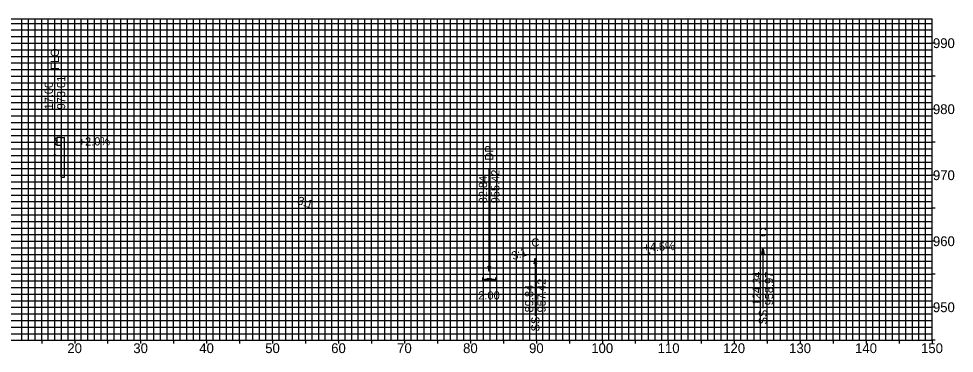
# Model space of a CAD drawing. Extents: x -153 to 153, y 943 to 994.
# Drawn here: x 11.5 to 153.4, y 943 to 993.7 of the extents above; entities that cross this region are included whole.
import ezdxf

# ---------------------------------------------------------------- set-up
doc = ezdxf.new("R2010")
doc.units = 0
for name, color, linetype in [('Default', 7, 'Continuous'), ('E_NCDOT_Terrain_Model_Boundary', 7, 'Continuous'), ('E_NCDOT_Terrain_Model_Breakline', 7, 'Continuous'), ('E_NCDOT_Terrain_Model_Contour_Imported', 7, 'Continuous'), ('E_NCDOT_Terrain_Model_Island', 7, 'Continuous'), ('E_NCDOT_Terrain_Model_Points_High', 7, 'Continuous'), ('E_NCDOT_Terrain_Model_Points_Low', 7, 'Continuous'), ('P_NCDOT_XS_Label_Grading_Side_Slope', 7, 'Continuous'), ('P_NCDOT_XS_Label_Slope_Superelevation', 7, 'Continuous'), ('Prop XS Grade Point', 7, 'Continuous'), ('Prop XS Label Slope Superelevation', 7, 'Continuous'), ('Prop XSC Text', 7, 'Continuous'), ('Sheet_Data_Field_CELL', 7, 'Continuous'), ('Sheet_RDY_Sticker_Preliminary_CELL', 7, 'Continuous'), ('Sheet_Sticker_Incomplete_CELL', 7, 'Continuous')]:
    doc.layers.add(name, color=color, linetype=linetype)

msp = doc.modelspace()

# ---------------------------------------------------------------- linework, layer by layer
at = {"layer": 'Default'}
msp.add_line((107.09, 958.2), (107.09, 958.2), dxfattribs=at)
at = {"layer": 'E_NCDOT_Terrain_Model_Breakline'}
for p, q in [((-150, 993), (150, 993)), ((12, 945), (12, 993.7)), ((13, 945), (13, 993.7)), ((14, 945), (14, 993.7)), ((16, 945), (16, 993.7)), ((17, 945), (17, 993.7)), ((18, 945), (18, 993.7)), ((19, 945), (19, 993.7)), ((21, 945), (21, 993.7)), ((22, 945), (22, 993.7)), ((23, 945), (23, 993.7)), ((24, 945), (24, 993.7)), ((26, 945), (26, 993.7)), ((27, 945), (27, 993.7)), ((28, 945), (28, 993.7)), ((29, 945), (29, 993.7)), ((31, 945), (31, 993.7)), ((32, 945), (32, 993.7)), ((33, 945), (33, 993.7)), ((34, 945), (34, 993.7)), ((36, 945), (36, 993.7)), ((37, 945), (37, 993.7)), ((38, 945), (38, 993.7)), ((39, 945), (39, 993.7)), ((41, 945), (41, 993.7)), ((42, 945), (42, 993.7)), ((43, 945), (43, 993.7)), ((44, 945), (44, 993.7)), ((46, 945), (46, 993.7)), ((47, 945), (47, 993.7)), ((48, 945), (48, 993.7)), ((49, 945), (49, 993.7)), ((51, 945), (51, 993.7)), ((52, 945), (52, 993.7)), ((53, 945), (53, 993.7)), ((54, 945), (54, 993.7)), ((56, 945), (56, 993.7)), ((57, 945), (57, 993.7)), ((58, 945), (58, 993.7)), ((59, 945), (59, 993.7)), ((61, 945), (61, 993.7)), ((62, 945), (62, 993.7)), ((63, 945), (63, 993.7)), ((64, 945), (64, 993.7)), ((66, 945), (66, 993.7)), ((67, 945), (67, 993.7)), ((68, 945), (68, 993.7)), ((69, 945), (69, 993.7)), ((71, 945), (71, 993.7)), ((72, 945), (72, 993.7)), ((73, 945), (73, 993.7)), ((74, 945), (74, 993.7)), ((76, 945), (76, 993.7)), ((77, 945), (77, 993.7)), ((78, 945), (78, 993.7)), ((79, 945), (79, 993.7)), ((81, 945), (81, 993.7)), ((82, 945), (82, 993.7)), ((83, 945), (83, 993.7)), ((84, 945), (84, 993.7)), ((86, 945), (86, 993.7)), ((87, 945), (87, 993.7)), ((88, 945), (88, 993.7)), ((89, 945), (89, 993.7)), ((91, 945), (91, 993.7)), ((92, 945), (92, 993.7)), ((93, 945), (93, 993.7)), ((94, 945), (94, 993.7)), ((96, 945), (96, 993.7)), ((97, 945), (97, 993.7)), ((98, 945), (98, 993.7)), ((99, 945), (99, 993.7)), ((101, 945), (101, 993.7)), ((102, 945), (102, 993.7)), ((103, 945), (103, 993.7)), ((104, 945), (104, 993.7)), ((106, 945), (106, 993.7)), ((107, 945), (107, 993.7)), ((108, 945), (108, 993.7)), ((109, 945), (109, 993.7)), ((111, 945), (111, 993.7)), ((112, 945), (112, 993.7)), ((113, 945), (113, 993.7)), ((114, 945), (114, 993.7)), ((116, 945), (116, 993.7)), ((117, 945), (117, 993.7)), ((118, 945), (118, 993.7)), ((119, 945), (119, 993.7)), ((121, 945), (121, 993.7)), ((122, 945), (122, 993.7)), ((123, 945), (123, 993.7)), ((124, 945), (124, 993.7)), ((126, 945), (126, 993.7)), ((127, 945), (127, 993.7)), ((128, 945), (128, 993.7)), ((129, 945), (129, 993.7)), ((131, 945), (131, 993.7)), ((132, 945), (132, 993.7)), ((133, 945), (133, 993.7)), ((134, 945), (134, 993.7)), ((136, 945), (136, 993.7)), ((137, 945), (137, 993.7)), ((138, 945), (138, 993.7)), ((139, 945), (139, 993.7)), ((141, 945), (141, 993.7)), ((142, 945), (142, 993.7)), ((143, 945), (143, 993.7)), ((144, 945), (144, 993.7)), ((146, 945), (146, 993.7)), ((147, 945), (147, 993.7)), ((148, 945), (148, 993.7)), ((149, 945), (149, 993.7)), ((-150, 992), (150, 992)), ((-150, 991), (150, 991)), ((-150, 989), (150, 989)), ((-150, 988), (150, 988)), ((-150, 987), (150, 987)), ((-150, 986), (150, 986)), ((-150, 984), (150, 984)), ((-150, 983), (150, 983)), ((-150, 982), (150, 982)), ((-150, 981), (150, 981)), ((-150, 979), (150, 979)), ((-150, 978), (150, 978)), ((-150, 977), (150, 977)), ((-150, 976), (150, 976)), ((-150, 974), (150, 974)), ((-150, 973), (150, 973)), ((-150, 972), (150, 972)), ((-150, 971), (150, 971)), ((-150, 969), (150, 969)), ((-150, 968), (150, 968)), ((-150, 967), (150, 967)), ((-150, 966), (150, 966)), ((-150, 964), (150, 964)), ((-150, 963), (150, 963)), ((-150, 962), (150, 962)), ((-150, 961), (150, 961)), ((-150, 959), (150, 959)), ((-150, 958), (150, 958)), ((-150, 957), (150, 957)), ((-150, 956), (150, 956)), ((-150, 954), (150, 954)), ((-150, 953), (150, 953)), ((-150, 952), (150, 952)), ((-150, 951), (150, 951)), ((-150, 949), (150, 949)), ((-150, 948), (150, 948)), ((-150, 947), (150, 947)), ((-150, 946), (150, 946))]:
    msp.add_line(p, q, dxfattribs=at)
at = {"layer": 'E_NCDOT_Terrain_Model_Contour_Imported'}
msp.add_circle((107.09, 958.2), 0.05, dxfattribs=at)
at = {"layer": 'E_NCDOT_Terrain_Model_Island'}
for p, q in [((20, 945), (20, 993.7)), ((30, 945), (30, 993.7)), ((40, 945), (40, 993.7)), ((50, 945), (50, 993.7)), ((60, 945), (60, 993.7)), ((70, 945), (70, 993.7)), ((80, 945), (80, 993.7)), ((90, 945), (90, 993.7)), ((100, 945), (100, 993.7)), ((110, 945), (110, 993.7)), ((120, 945), (120, 993.7)), ((130, 945), (130, 993.7)), ((140, 945), (140, 993.7)), ((-150, 990), (150, 990)), ((-150, 980), (150, 980)), ((-150, 970), (150, 970)), ((-150, 960), (150, 960)), ((-150, 950), (150, 950))]:
    msp.add_line(p, q, dxfattribs=at)
at = {"layer": 'E_NCDOT_Terrain_Model_Points_High'}
for p, q in [((15, 945), (15, 993.7)), ((20, 945), (20, 993.7)), ((25, 945), (25, 993.7)), ((30, 945), (30, 993.7)), ((35, 945), (35, 993.7)), ((40, 945), (40, 993.7)), ((45, 945), (45, 993.7)), ((50, 945), (50, 993.7)), ((55, 945), (55, 993.7)), ((60, 945), (60, 993.7)), ((65, 945), (65, 993.7)), ((70, 945), (70, 993.7)), ((75, 945), (75, 993.7)), ((80, 945), (80, 993.7)), ((85, 945), (85, 993.7)), ((90, 945), (90, 993.7)), ((95, 945), (95, 993.7)), ((100, 945), (100, 993.7)), ((105, 945), (105, 993.7)), ((110, 945), (110, 993.7)), ((115, 945), (115, 993.7)), ((120, 945), (120, 993.7)), ((125, 945), (125, 993.7)), ((130, 945), (130, 993.7)), ((135, 945), (135, 993.7)), ((140, 945), (140, 993.7)), ((145, 945), (145, 993.7)), ((-150, 990), (150, 990)), ((150.48, 990), (150, 990)), ((-150, 985), (150, 985)), ((150.48, 985), (150, 985)), ((-150, 980), (150, 980)), ((150.48, 980), (150, 980)), ((-150, 975), (150, 975)), ((150.48, 975), (150, 975)), ((-150, 970), (150, 970)), ((150.48, 970), (150, 970)), ((-150, 965), (150, 965)), ((150.48, 965), (150, 965)), ((-150, 960), (150, 960)), ((150.48, 960), (150, 960)), ((-150, 955), (150, 955)), ((150.48, 955), (150, 955)), ((-150, 950), (150, 950)), ((150.48, 950), (150, 950)), ((15, 945), (15, 944.52)), ((20, 945), (20, 944.52)), ((25, 945), (25, 944.52)), ((30, 945), (30, 944.52)), ((35, 945), (35, 944.52)), ((40, 945), (40, 944.52)), ((45, 945), (45, 944.52)), ((50, 945), (50, 944.52)), ((55, 945), (55, 944.52)), ((60, 945), (60, 944.52)), ((65, 945), (65, 944.52)), ((70, 945), (70, 944.52)), ((75, 945), (75, 944.52)), ((80, 945), (80, 944.52)), ((85, 945), (85, 944.52)), ((90, 945), (90, 944.52)), ((95, 945), (95, 944.52)), ((100, 945), (100, 944.52)), ((105, 945), (105, 944.52)), ((110, 945), (110, 944.52)), ((115, 945), (115, 944.52)), ((120, 945), (120, 944.52)), ((125, 945), (125, 944.52)), ((130, 945), (130, 944.52)), ((135, 945), (135, 944.52)), ((140, 945), (140, 944.52)), ((145, 945), (145, 944.52)), ((150, 945), (150, 944.52)), ((150.48, 945), (150, 945))]:
    msp.add_line(p, q, dxfattribs=at)
at = {"layer": 'E_NCDOT_Terrain_Model_Points_Low'}
for p, q in [((-150, 993.7), (150, 993.7)), ((150, 945), (150, 993.7)), ((-150, 945), (150, 945))]:
    msp.add_line(p, q, dxfattribs=at)
at = {"layer": 'Prop XS Grade Point'}
for p, q in [((17, 973.01), (17, 985.49)), ((82.84, 955.42), (82.84, 971.02)), ((124.34, 958.97), (124.34, 949.87)), ((89.84, 957.42), (89.84, 948.75)), ((89.84, 957.42), (89.84, 948.68)), ((81.84, 954.52), (81.84, 953.92)), ((81.84, 954.22), (83.84, 954.22)), ((83.84, 953.92), (83.84, 954.52))]:
    msp.add_line(p, q, dxfattribs=at)
for points in [[(124.34, 958.97), (124.52, 958.15), (124.17, 958.15)], [(82.84, 955.42), (82.67, 956.25), (83.02, 956.25)], [(89.84, 957.42), (90.02, 956.6), (89.67, 956.6)], [(89.84, 957.42), (90.02, 956.6), (89.67, 956.6)], [(89.84, 957.42), (90.02, 956.6), (89.67, 956.6)], [(81.84, 954.22), (83.03, 954.42), (83.03, 954.03)], [(83.84, 954.22), (82.66, 954.03), (82.66, 954.42)]]:
    msp.add_lwpolyline(points, close=True, dxfattribs=at)
msp.add_circle((17, 973.01), 0.12, dxfattribs=at)
at = {"layer": 'Prop XSC Text'}
for p, q in [((17.17, 975.62), (17.03, 975.52)), ((17.03, 975.39), (17.24, 975.25)), ((17.24, 975.03), (17.03, 974.88)), ((17.03, 974.75), (17.17, 974.66)), ((17.27, 975.64), (17.18, 975.63)), ((17.18, 974.65), (17.27, 974.63)), ((17.94, 975.72), (17.28, 975.72)), ((17.28, 975.72), (17.28, 974.55)), ((17.28, 975.19), (17.28, 975.14)), ((17.28, 975.14), (17.28, 975.09)), ((17.28, 974.55), (17.94, 974.55)), ((17.94, 975.72), (18.44, 975.72)), ((17.96, 975.72), (17.94, 975.72)), ((17.94, 975.72), (17.94, 969.72)), ((17.96, 969.72), (17.96, 975.72)), ((18.44, 975.72), (18.43, 975.72)), ((18.43, 975.72), (18.43, 969.72)), ((18.44, 969.72), (18.44, 975.72)), ((17.94, 969.72), (18.44, 969.72)), ((17.94, 969.72), (17.96, 969.72)), ((18.43, 969.72), (18.44, 969.72))]:
    msp.add_line(p, q, dxfattribs=at)
for centre, radius, start, end in [((17.08, 975.46), 0.0787, 125.2976, 235.3478), ((17.08, 974.82), 0.0787, 124.6522, 234.7024), ((17.19, 975.59), 0.0328, 100, 125.2976), ((17.19, 974.68), 0.0328, 234.7024, 260), ((17.2, 975.19), 0.0787, 0.02, 55.3478), ((17.2, 975.09), 0.0787, 304.6522, 359.98)]:
    msp.add_arc(centre, radius, start, end, dxfattribs=at)
at = {"layer": 'Sheet_Data_Field_CELL'}
msp.add_line((15, 973.05), (15, 973.68), dxfattribs=at)

# ---------------------------------------------------------------- texts
at = {"layer": 'E_NCDOT_Terrain_Model_Boundary'}
for s, p in [('990', (150.12, 989.26)), ('980', (150.12, 979.26)), ('970', (150.12, 969.26)), ('960', (150.12, 959.26)), ('950', (150.12, 949.26)), ('20', (18.89, 943.06)), ('30', (28.89, 943.06)), ('40', (38.89, 943.06)), ('50', (48.89, 943.06)), ('60', (58.89, 943.06)), ('70', (68.89, 943.06)), ('80', (78.89, 943.06)), ('90', (88.89, 943.06)), ('100', (98.32, 943.06)), ('110', (108.39, 943.06)), ('120', (118.32, 943.06)), ('130', (128.32, 943.06)), ('140', (138.32, 943.06)), ('150', (148.32, 943.06))]:
    msp.add_text(s, height=1.488, dxfattribs=at).set_placement(p)
at = {"layer": 'P_NCDOT_XS_Label_Grading_Side_Slope'}
for s, rotation, p in [('+2.0%', 1.1458, (20.61, 974.45)), ('3:1', 341.5651, (53.66, 965.66)), ('3:1', 18.4349, (86.48, 957.14)), ('3:1', 18.4349, (86.48, 957.14)), ('+4.5%', 2.5619, (106.25, 958.45))]:
    msp.add_text(s, height=1.248, rotation=rotation, dxfattribs=at).set_placement(p)
at = {"layer": 'P_NCDOT_XS_Label_Slope_Superelevation'}
for s, p in [('973.01', (18.56, 979.97)), ('17.00', (16.69, 979.97))]:
    msp.add_text(s, height=1.248, rotation=90, dxfattribs=at).set_placement(p)
at = {"layer": 'Prop XS Label Slope Superelevation'}
for s, p in [('DP', (83.47, 972.22)), ('955.42', (84.4, 965.74)), ('82.84', (82.53, 965.74)), ('124.34', (124.03, 950.29)), ('958.97', (125.9, 950.29)), ('89.84', (89.53, 949.22)), ('957.42', (91.4, 949.22)), ('SS', (124.97, 947.41)), ('SS', (90.47, 946.34))]:
    msp.add_text(s, height=1.248, rotation=90, dxfattribs=at).set_placement(p)
for p in [(123.74, 960.74), (89.24, 959.2)]:
    msp.add_text('C', height=1.25, dxfattribs=at).set_placement(p)
at = {"layer": 'Sheet_RDY_Sticker_Preliminary_CELL'}
msp.add_text('2.00', height=1.248, dxfattribs=at).set_placement((81.19, 951.18))
at = {"layer": 'Sheet_Sticker_Incomplete_CELL'}
msp.add_text('FLO', height=1.248, rotation=90, dxfattribs=at).set_placement((17.62, 985.97))

doc.saveas('drawing.dxf')
